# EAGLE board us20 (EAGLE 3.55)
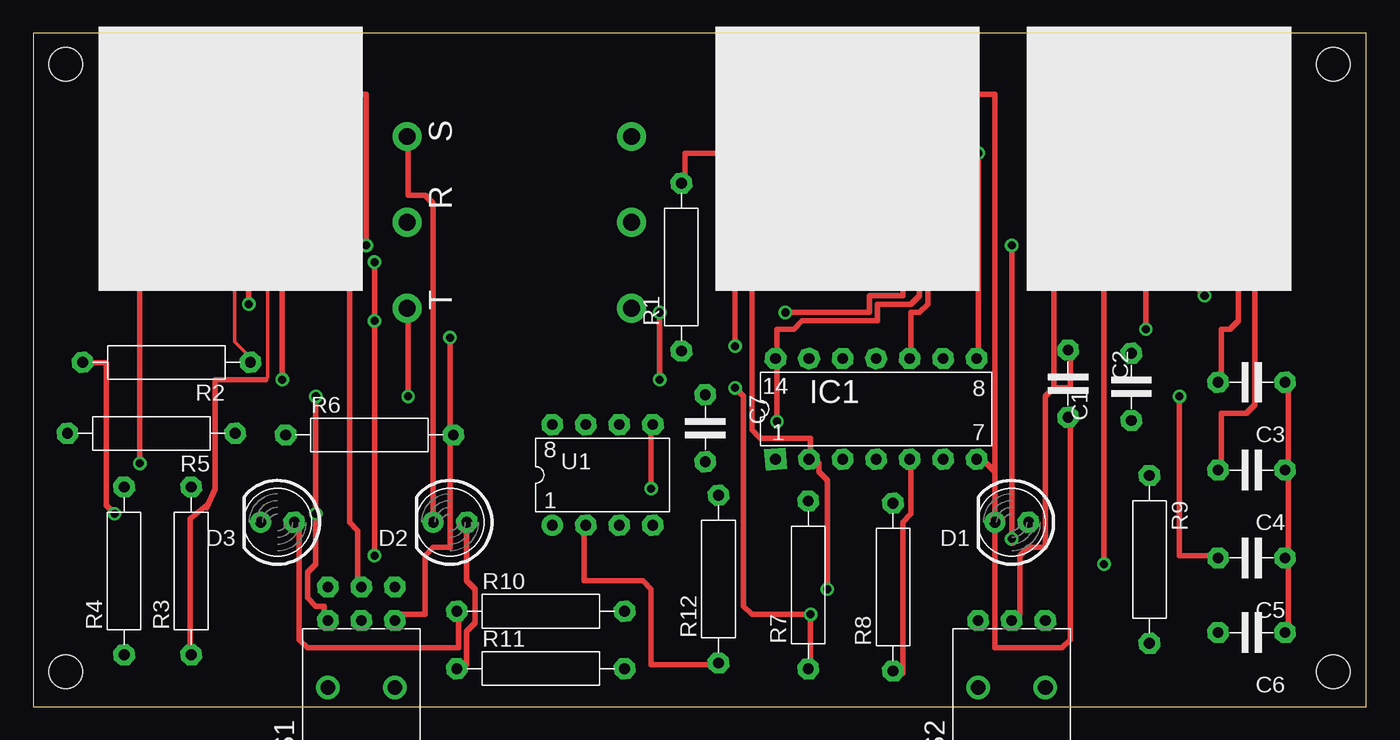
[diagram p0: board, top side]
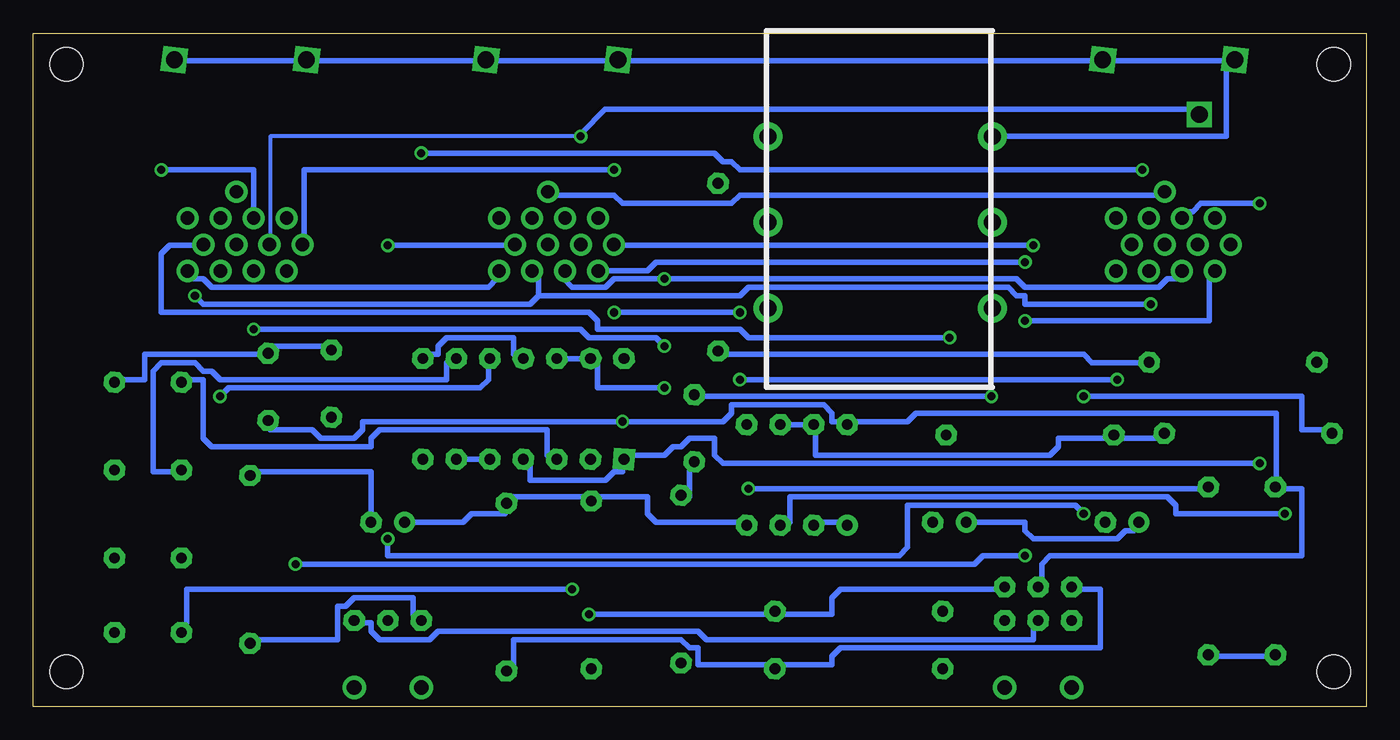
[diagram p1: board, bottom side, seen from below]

Size 101 x 51 mm. Coordinates in mm from the lower left corner, seen from the top.
Outline: 0,0 101,0 101,51 0,51 0,0
Copper layers used: Top, Bottom
Holes 2.54 mm at 2.47,2.63 98.47,2.63 98.47,48.63 2.47,48.63

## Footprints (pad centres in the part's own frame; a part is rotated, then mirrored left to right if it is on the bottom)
5 = drill 0.813 pad 1.6 octagon:  -2.54,0;  2.54,0
D5 = drill 0.813 pad 1.6 octagon:  -1.27,0 | drill 0.813 pad 1.6 round:  1.27,0
L14 = drill 0.813 pad 1.6 square:  -7.62,-3.81 | drill 0.813 pad 1.6 octagon:  -5.08,-3.81;  7.62,-3.81;  7.62,3.81;  -2.54,-3.81;  0,-3.81;  5.08,-3.81;  2.54,-3.81;  5.08,3.81;  2.54,3.81;  0,3.81;  -2.54,3.81;  -5.08,3.81;  -7.62,3.81
12,5 = drill 0.813 pad 1.6 octagon:  -6.35,0;  6.35,0
70-2W = drill 0.813 pad 1.6 octagon:  5.08,-2.54;  5.08,0;  5.08,2.54;  7.62,-2.54;  7.62,0;  7.62,2.54 | drill 1.118 pad 1.778 round:  0,-2.54;  0,2.54
70-1W = drill 0.813 pad 1.6 octagon:  5.08,-2.54;  5.08,0;  5.08,2.54 | drill 1.118 pad 1.778 round:  0,-2.54;  0,2.54
L08 = drill 0.813 pad 1.6 round:  -3.81,-3.81 | drill 0.813 pad 1.6 octagon:  -1.27,-3.81;  1.27,-3.81;  3.81,-3.81;  3.81,3.81;  1.27,3.81;  -1.27,3.81;  -3.81,3.81
N13PLU = drill 1.016 pad 1.676 round: 0 -1,-4.5; 1 1.5,-4.5; 2 4,-4.5; 3 0.3,-2.5;  0.3,-6.5;  2.8,-6.5;  -2.2,-6.5;  -4.7,-6.5;  -3.5,-4.5;  -3.5,-8.5;  -1,-8.5;  1.5,-8.5;  4,-8.5 | drill 1.27 pad 1.676 square: 4 -5,7.5; 5 5,7.5
INKE = drill 1.27 pad 2.184 round: EVE 5.5,8.5; G -1,8.5;  5.5,-8.5;  -1,-8.5;  -7.5,8.5;  -7.5,-8.5

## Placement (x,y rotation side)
C1  1æ  [5]  83.19,24.21 90 top
C2  1æ  [5]  78.4,24.45 270 top
C3  100n  [5]  92.3,24.56 180 top
C4  100n  [5]  92.3,17.91 180 top
C5  100n  [5]  92.3,11.26 180 top
C6  100n  [5]  92.3,5.61 180 top
C7  470n  [5]  50.92,21.08 270 top
D1  LED5  [D5]  74.13,13.95 180 top
D2  LED5  [D5]  31.58,13.95 180 top
D3  LED5  [D5]  18.52,13.95 180 top
IC1  4066  [L14]  63.86,22.54 0 top
R1  10K  [12,5]  49.11,33.27 90 top
R2  1K  [12,5]  10.11,26.07 180 top
R3  1K  [12,5]  11.98,10.27 90 top
R4  68K  [12,5]  6.9,10.27 90 top
R5  1K  [12,5]  8.96,20.69 180 top
R6  1K  [12,5]  25.49,20.57 0 top
R7  100k  [12,5]  58.72,9.21 90 top
R8  100k  [12,5]  65.14,9.05 90 top
R9  1k  [12,5]  84.56,11.14 270 top
R10  1k  [12,5]  38.46,7.22 0 top
R11  1k  [12,5]  38.46,2.87 0 top
R12  470  [12,5]  51.92,9.65 90 top
S1  9070-2W  [70-2W]  24.87,1.44 90 top
S2  9070-1W  [70-1W]  74.13,1.44 90 top
U1  TL072  [L08]  43.14,17.54 0 top
U$1  DIN13PLUG  [N13PLU]  14.98,41.48 0 top
U$2  470  [N13PLU]  61.7,41.48 0 top
U$3  DIN13PLUG  [N13PLU]  85.29,41.48 0 top
U$4  KLINKE  [INKE]  36.84,37.67 90 top

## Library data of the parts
C1-C7 R1-R12 = discrete
D1-D3 = led
IC1 = 40xx
S1 S2 = switch
U1 = linear
U$1-U$4 = con-din1

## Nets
GND: C1. C2. C3. C4. C5. C6. D2. D3. R1. S2. U$1.4 U$1.5 U$2.4 U$2.5 U$3.4 U$3.5 U$4.EVE
N$1: U$1. U$2. U$3.
N$2: U$1. U$2. U$3.
N$3: U$1. U$2. U$3.
N$4: U$1. U$2. U$3.
N$5: U$1. U$2. U$3.
N$6: U$1. U$2. U$3.
N$7: R2. U1.
N$8: R3. U1.
N$9: R12. U1.
N$10: R1. R2. U$1.
N$11: R3. R4. U$1.
N$12: R5. R6. U1.
N$13: R5. S1. U$2.
N$14: R6. S1. U$3.
N$15: C6. IC1. U$2.0
N$16: C5. IC1. U$2.1
N$17: IC1. U$1.0
N$18: IC1. U$1.1
N$19: C3. IC1. U$3.0
N$20: C4. IC1. U$3.1
N$21: S1. S2.
N$22: IC1. R8. R11. S1.
N$23: IC1. R7. R10. S1.
N$24: D1. R9.
N$25: D3. R10.
N$26: D2. R11.
N$27: R9. S2.
N$28: C7. R12.
N$29: C7. U$4.
V+: C1. IC1. R4. S1. U1. U$1.2 U$2.2
V-: C2. D1. IC1. R7. R8. U1. U$1.3 U$2.3

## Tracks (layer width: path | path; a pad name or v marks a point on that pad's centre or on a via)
GND
  Top 0.4: R1. 49.37,40 49.37,41.91 53.81,41.91 53.81,45.72 56.98,45.72 56.98,48.26 U$2.4
  Top 0.406: D2. 30.31,38.1 29.68,38.73 28.41,38.73 28.41,42.54 U$4.EVE | 94.84,5.61 95.08,6.34 95.08,10.79 94.84,11.26 95.08,12.06 95.08,17.14 94.84,17.91 95.08,18.41 95.08,24.12 94.84,24.56 | 77.3,24.12 76.67,23.49 76.67,12.06 75.4,12.06 74.77,11.43 74.77,6.98 74.13,6.52 | 77.3,24.12 78.58,24.12 78.58,26.66 78.4,26.99 | 77.3,24.12 77.3,44.45 77.94,45.08 80.48,45.08 80.48,48.89 U$3.4
  Bottom 0.4: U$1.4 10.63,48.89 19.52,48.89 U$1.5 20.79,48.89 56.35,48.89 | 10.63,43.18 10.63,48.26
  Bottom 0.406: D3. 17.61,13.33 18.25,13.33 18.88,12.7 25.23,12.7 25.87,13.33 25.87,13.97 29.68,13.97 D2. | 78.4,26.99 78.58,27.3 83.02,27.3 C1. 83.66,26.66 92.55,26.66 92.55,24.76 94.45,24.76 94.84,24.56 | U$3.5 90,48.89 80.48,48.89 U$3.4 79.84,48.89 67.14,48.89 U$2.5 66.51,48.89 56.98,48.89 U$2.4 56.35,48.89 | 10.63,43.18 27.77,43.18 U$4.EVE | 10.63,48.26 U$1.4
N$1  (via drill 0.61 pad 1.02)
  Top 0.4: v25.87,33.65 v25.87,29.2 v25.87,11.43 | v81.11,10.79 81.11,33.02 81.79,32.98
  Bottom 0.4: v25.87,29.2 11.9,29.2 11.9,32.38 11.48,32.98 | v25.87,33.65 53.81,33.65 54.45,33.02 57.62,33.02 58.2,32.98 | v81.11,10.79 29.68,10.79 29.04,11.43 v25.87,11.43
N$2  (via drill 0.61 pad 1.02)
  Top 0.406: v53.17,32.38 v53.17,27.3 | v84.29,28.57 84.29,32.98
  Bottom 0.406: 13.98,32.98 13.81,32.38 15.08,32.38 15.71,31.74 25.87,31.74 26.5,32.38 v53.17,32.38 56.98,32.38 57.62,31.74 60.16,31.74 60.8,32.38 60.7,32.98 | v84.29,28.57 59.52,28.57 58.89,27.93 53.81,27.93 v53.17,27.3
N$3  (via drill 0.61 pad 1.02)
  Top 0.4: v88.73,31.11 88.1,31.74 88.1,32.38 87.47,33.02 86.79,32.98
  Top 0.406: v16.34,30.47 16.34,32.38 16.48,32.98
  Bottom 0.4: 62.7,31.11 62.7,32.38 63.2,32.98 | 62.7,31.11 47.46,31.11 46.82,31.74 27.14,31.74 26.5,31.11 25.87,31.11 25.87,30.47 | v88.73,31.11 88.1,30.47 63.34,30.47 62.7,31.11
  Bottom 0.406: v16.34,30.47 25.87,30.47
N$4  (via drill 0.61 pad 1.02)
  Top 0.4: v47.46,24.76 v47.46,29.84 | v56.98,29.84 63.34,29.84 63.34,31.11 65.88,31.11 65.88,32.38 U$2. | v18.88,24.76 18.88,32.38 U$1.
  Bottom 0.4: v47.46,29.84 v56.98,29.84 | 22.7,24.76 22.48,24.76 | 22.7,24.76 v47.46,24.76 | v18.88,24.76 22.7,24.76
  Bottom 0.406: U$3. 89.37,32.38 88.1,32.38 87.47,31.74 66.51,31.74 65.88,32.38 U$2.
N$5  (via drill 0.61 pad 1.02)
  Top 0.406: v25.23,34.92 25.23,46.35 10.63,46.35 10,45.72 10,34.92 10.28,34.98 | v56.98,40.64 56.98,35.55 57,34.98
  Bottom 0.406: v25.23,34.92 56.98,34.92 57,34.98 | v56.98,40.64 80.48,40.64 80.48,35.55 80.59,34.98
N$6  (via drill 0.61 pad 1.02, 1.27 pad 1.02)
  Top 0.25: v59.52,43.18 59.52,35.55 59.5,34.98
  Top 0.406: 12.78,34.98 12.78,44.83 v12.67,44.83
  Bottom 0.2: 59.47,43.23 v59.52,43.18 59.47,43.43
  Bottom 0.3: v59.52,43.18 83.02,43.18 83.02,35.55 83.09,34.98
  Bottom 0.406: v12.67,44.83 12.67,45.23 57.67,45.23 59.47,43.43
N$7  (via drill 0.61 pad 1.02)
  Top 0.4: v6.18,14.6 5.55,15.24 5.55,26.03
  Top 0.406: 5.55,26.03 4.28,26.03 R2.
  Bottom 0.4: v6.18,14.6 14.44,14.6 14.44,15.24 15.08,15.87 43.65,15.87 43.65,13.97 44.41,13.73
N$8  (via drill 0.61 pad 1.02)
  Top 0.406: v46.82,16.5 46.82,20.95 46.95,21.35
  Bottom 0.406: v46.82,16.5 12.54,16.5 R3.
N$9
  Top 0.406: 51.92,3.3 51.27,3.17 46.82,3.17 46.82,8.89 46.19,9.52 41.74,9.52 41.74,13.33 41.87,13.73
  Bottom 0.406: 39.33,13.73 39.84,13.97 41.11,13.97 41.87,13.73
N$10
  Top 0.254: 16.46,26.07 16.46,26.44 15.27,27.63 15.27,34.83 15.28,34.84 15.28,34.98
  Bottom 0.4: 49.11,26.92 48.73,26.66 21.42,26.66 20.79,26.03 16.98,26.03 16.46,26.07
N$11
  Top 0.254: 17.61,24.76 17.61,24.77 17.78,24.94 17.78,34.98
  Top 0.406: 17.61,24.76 13.81,24.76 13.81,16.5 13.17,15.07 13.17,15.24 11.9,14.24 11.9,4.44 11.98,3.92
  Bottom 0.406: 6.9,3.92 7.46,3.8 11.27,3.8 11.98,3.92
N$12
  Bottom 0.406: 44.41,21.35 41.87,21.35 41.74,20.95 41.74,19.04 23.96,19.04 23.33,19.68 23.33,20.31 19.52,20.31 19.14,20.57 18.88,20.31 15.71,20.31 15.31,20.69
N$13  (via drill 0.61 pad 1.02)
  Top 0.406: v21.42,23.49 v21.42,14.6 21.42,10.79 20.79,10.16 20.79,8.25 21.42,7.62 22.06,7.62 22.06,6.98 22.33,6.52 | v74.13,12.7 v74.13,34.92
  Bottom 0.406: v21.42,23.49 4.92,23.49 4.92,20.95 3.01,20.95 R5. | v74.13,34.92 65.24,34.92 64.5,34.98 | v74.13,12.7 74.13,11.43 35.39,11.43 34.76,12.06 34.76,15.24 22.06,15.24 v21.42,14.6
N$14  (via drill 0.61 pad 1.02)
  Top 0.406: v31.58,27.93 31.58,20.95 R6. 31.58,20.31 31.58,12.06 30.31,12.06 29.68,11.43 29.68,6.98 27.77,6.98 27.41,6.52
  Bottom 0.406: v31.58,27.93 46.82,27.93 47.46,28.57 58.25,28.57 58.25,29.2 58.89,29.84 91.28,29.84 91.28,34.29 90.64,34.92 88.1,34.92 88.09,34.98
N$15  (via drill 0.61 pad 1.02)
  Top 0.4: v60.16,8.89 60.16,17.14
  Top 0.406: U$2.0 60.8,37.46 60.8,44.45 60.16,45.08 54.45,45.08 54.45,20.95 55.08,20.31 58.89,20.31 58.89,19.04 58.78,18.73 59.52,18.41 59.52,17.77 60.16,17.14
  Bottom 0.4: v60.16,8.89 89.37,8.89 89.37,6.34 C6.
N$16  (via drill 0.61 pad 1.02)
  Top 0.406: U$2.1 63.34,37.46 64.61,37.46 64.61,38.1 67.78,38.1 67.78,30.47 67.14,29.84 66.51,29.84 66.51,26.66 66.4,26.35 | v86.83,23.49 86.83,11.43 89.37,11.43 C5.
  Bottom 0.406: v86.83,23.49 86.19,24.12 67.14,24.12 66.51,24.76 66.51,26.03 66.4,26.35
N$17  (via drill 0.61 pad 1.02)
  Top 0.406: v8.09,18.41 v8.09,38.1
  Bottom 0.406: v8.09,38.1 12.54,38.1 13.17,37.46 13.81,37.46 U$1.0 | v8.09,18.41 48.73,18.41 49.37,19.04 49.37,20.31 51.27,20.31 51.91,19.68 52.54,19.68 53.17,19.04 55.71,19.04 56.24,18.73 56.35,18.41 56.35,17.77 56.98,17.77 57.62,17.14 63.34,17.14 63.34,18.41 63.86,18.73
N$18  (via drill 0.61 pad 1.02)
  Top 0.4: v16.98,40.64 16.98,37.46 U$1.1 | v71.59,41.91 71.59,26.66 71.48,26.35
  Bottom 0.4: v16.98,40.64 47.46,40.64 48.09,41.27 48.73,41.27 49.37,41.91 v71.59,41.91
  Bottom 0.406: 63.86,26.35 64.61,26.66 64.61,27.93 69.69,27.93 70.32,27.3 70.32,26.66 70.95,26.66 71.48,26.35
N$19  (via drill 0.61 pad 1.02)
  Top 0.406: v91.28,40.64 91.28,29.2 90.64,28.57 90,28.57 90,24.76 C3.
  Bottom 0.406: v91.28,40.64 84.29,40.64 U$3.0 | 61.32,18.73 62.06,19.04 62.06,20.95 74.77,20.95 75.4,20.31 75.4,19.68 87.47,19.68 88.1,20.31 88.1,24.76 89.37,24.76 C3.
N$20
  Top 0.406: U$3.1 86.83,37.46 86.83,40 87.47,40.64 87.47,41.27 90,41.27 90,41.91 90.64,42.54 92.55,42.54 92.55,22.86 91.91,22.22 90,22.22 90,18.41 C4.
  Bottom 0.406: 68.94,26.35 69.69,26.03 69.69,24.76 86.83,24.76 87.47,25.39 88.1,25.39 88.73,26.03 91.28,26.03 91.91,25.39 91.91,17.77 90,17.77 C4.
N$21
  Bottom 0.406: 24.87,6.52 25.23,6.34 25.23,5.08 50,5.08 50.63,5.71 70.32,5.71 70.95,5.08 74.77,5.08 75.4,5.71 75.4,6.34 76.03,6.34 76.67,6.52
N$22
  Top 0.406: 65.14,2.7 65.88,2.54 65.88,13.97 66.51,14.6 66.51,18.41 66.4,18.73
  Bottom 0.406: 66.4,18.73 68.94,18.73 | 65.14,2.7 64.61,3.17 64.61,5.08 51.91,5.08 51.27,4.44 50.63,4.44 50.63,3.17 45.55,3.17 R11. 44.28,3.17 40.48,3.17 40.48,3.8 39.84,4.44 20.15,4.44 20.15,8.89 22.06,8.89 S1.
N$23  (via drill 0.61 pad 1.02)
  Top 0.406: 58.72,2.86 58.89,3.17 v58.89,6.98 54.45,6.98 53.81,7.62 53.81,23.49 v53.17,24.12
  Bottom 0.406: 61.32,26.35 58.78,26.35 58.25,26.03 58.25,24.12 v53.17,24.12 | v58.89,6.98 45.55,6.98 R10. 44.28,6.98 40.48,6.98 40.48,8.25 39.84,8.89 27.77,8.89 27.41,9.06
N$24
  Bottom 0.406: 75.4,13.95 75.4,17.77 84.29,17.77 84.56,17.49
N$25
  Top 0.4: 32.22,6.98 32.22,4.44 20.79,4.44 20.15,5.08 20.15,13.33 19.79,13.95
  Top 0.406: 32.22,6.98 32.11,7.22
N$26
  Top 0.4: 32.11,2.87 32.85,3.17 32.85,5.71 33.49,6.34 33.49,8.89 32.85,9.52 32.85,13.95
N$27
  Bottom 0.406: 71.59,6.52 72.22,6.98 72.22,8.25 76.67,8.25 77.3,7.62 77.94,7.62 77.94,5.08 84.29,5.08 R9.
N$28
  Bottom 0.406: C7. 51.27,17.77 51.27,15.87 R12.
N$29  (via drill 0.61 pad 1.02)
  Top 0.406: v28.41,23.49 28.41,29.84 28.34,30.17
  Bottom 0.406: v28.41,23.49 50.63,23.49 50.92,23.62
N$30  (via drill 0.61 pad 1.02)
  other vias: 12.67,44.83
V+  (via drill 0.61 pad 1.02)
  Top 0.406: U$2.2 65.88,36.83 67.14,36.83 67.14,31.11 66.51,30.47 63.97,30.47 63.97,29.2 58.25,29.2 57.62,28.57 56.35,28.57 56.35,26.66 IC1. 56.35,26.03 v56.35,21.58 | U$1.2 18.88,37.46 18.88,40.64 19.52,41.27 23.96,41.27 23.96,13.97 24.6,13.33 24.6,9.52 24.87,9.06
  Bottom 0.406: 83.19,21.67 83.02,20.95 79.84,20.95 79.21,20.31 76.67,20.31 76.03,20.95 76.03,21.58 v56.35,21.58 48.73,21.58 48.09,22.22 48.09,22.86 41.11,22.86 40.48,22.22 40.48,21.58 39.84,21.58 U1. 38.57,21.58 34.76,21.58 34.12,22.22 6.82,22.22 6.82,17.14 R4. 6.18,16.5 4.92,16.5 4.92,11.43 23.96,11.43 24.6,10.79 24.6,9.52 24.87,9.06
  other vias: 56.24,26.35
V-
  Top 0.406: 72.86,17.77 72.22,18.41 71.48,18.73 | 72.86,17.77 D1. 72.86,4.44 77.94,4.44 78.58,5.08 78.58,21.58 C2. | 72.86,17.77 72.86,46.35 68.41,46.35 67.78,45.72 67.78,41.27 62.06,41.27 62.06,39.37 U$2.3
  Bottom 0.406: U$1.3 15.71,38.73 47.46,38.73 48.09,38.1 56.35,38.1 56.98,38.73 61.43,38.73 U$2.3 | 46.95,13.73 47.46,13.97 53.81,13.97 54.45,14.6 54.45,15.87 58.25,15.87 R7. 58.89,15.87 64.61,15.87 R8. 65.24,14.6 67.78,14.6 68.41,13.97 72.22,13.97 D1.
